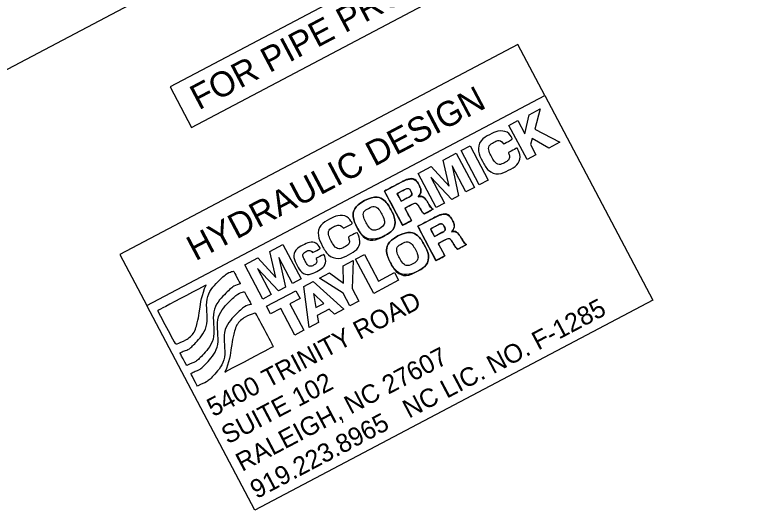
# Model space of a CAD drawing. Extents: x 1487051 to 1489241, y 497582 to 499399.
# Drawn here: x 1489072.9 to 1489240.5, y 498334.8 to 498446.4 of the extents above; entities that cross this region are included whole.
import ezdxf

# ---------------------------------------------------------------- set-up
doc = ezdxf.new("R2010")
doc.units = 0
doc.layers.add('COGO Default Point Elevation', color=7, linetype='Continuous')
doc.layers.add('Exist Vegetation Woods Line Cogo Elevation', color=7, linetype='Continuous')

msp = doc.modelspace()

# ---------------------------------------------------------------- linework, layer by layer
at = {"layer": 'Exist Vegetation Woods Line Cogo Elevation'}
for p, q in [((1489188.74, 498423.91), (1489191.24, 498425.23)), ((1489191.24, 498425.23), (1489189.99, 498420.68)), ((1489184.19, 498421.51), (1489186.2, 498422.57)), ((1489186.2, 498422.57), (1489187.76, 498419.61)), ((1489187.76, 498419.61), (1489188.74, 498423.91)), ((1489188.26, 498413.79), (1489184.19, 498421.51)), ((1489189.99, 498420.68), (1489195.67, 498417.7)), ((1489189.38, 498418.53), (1489189.02, 498417.23)), ((1489193.17, 498416.38), (1489189.38, 498418.53)), ((1489195.67, 498417.7), (1489193.17, 498416.38)), ((1489173.44, 498415.83), (1489175.45, 498416.89)), ((1489177.51, 498408.11), (1489173.44, 498415.83)), ((1489175.45, 498416.89), (1489179.52, 498409.17)), ((1489189.02, 498417.23), (1489190.27, 498414.85)), ((1489169.35, 498413.67), (1489172.31, 498415.24)), ((1489172.31, 498415.24), (1489176.39, 498407.52)), ((1489190.27, 498414.85), (1489188.26, 498413.79)), ((1489163.71, 498410.69), (1489166.67, 498412.26)), ((1489166.67, 498412.26), (1489170.72, 498407.81)), ((1489170.74, 498407.82), (1489169.35, 498413.67)), ((1489171.4, 498412.38), (1489171.38, 498412.37)), ((1489171.38, 498412.37), (1489172.85, 498405.65)), ((1489174.5, 498406.52), (1489171.4, 498412.38)), ((1489167.78, 498402.97), (1489163.71, 498410.69)), ((1489166.6, 498409.84), (1489166.58, 498409.83)), ((1489166.58, 498409.83), (1489169.67, 498403.97)), ((1489171.32, 498404.84), (1489166.6, 498409.84)), ((1489179.52, 498409.17), (1489177.51, 498408.11)), ((1489170.72, 498407.81), (1489170.74, 498407.82)), ((1489176.39, 498407.52), (1489174.5, 498406.52)), ((1489172.85, 498405.65), (1489171.32, 498404.84)), ((1489163.76, 498405.47), (1489163.77, 498405.44)), ((1489169.67, 498403.97), (1489167.78, 498402.97)), ((1489167.11, 498402.62), (1489165.12, 498401.57)), ((1489171.27, 498397.52), (1489171.28, 498397.49)), ((1489130.32, 498393.07), (1489133.29, 498394.63)), ((1489133.29, 498394.63), (1489137.36, 498386.91)), ((1489174.63, 498394.67), (1489172.64, 498393.62)), ((1489131.71, 498387.22), (1489130.32, 498393.07)), ((1489149.65, 498391.36), (1489151.66, 498392.42)), ((1489151.66, 498392.42), (1489154.83, 498386.43)), ((1489124.68, 498390.09), (1489127.64, 498391.65)), ((1489127.64, 498391.65), (1489131.69, 498387.21)), ((1489132.38, 498391.77), (1489132.35, 498391.76)), ((1489132.35, 498391.76), (1489133.83, 498385.04)), ((1489135.47, 498385.91), (1489132.38, 498391.77)), ((1489146.84, 498389.87), (1489149.12, 498391.08)), ((1489149.12, 498391.08), (1489148.87, 498384.75)), ((1489153.73, 498383.64), (1489149.65, 498391.36)), ((1489128.76, 498382.37), (1489124.68, 498390.09)), ((1489127.58, 498389.24), (1489127.55, 498389.23)), ((1489127.55, 498389.23), (1489130.65, 498383.37)), ((1489132.29, 498384.23), (1489127.58, 498389.24)), ((1489146.96, 498385.92), (1489146.84, 498389.87)), ((1489131.69, 498387.21), (1489131.71, 498387.22)), ((1489141.49, 498387.04), (1489143.77, 498388.25)), ((1489143.77, 498388.25), (1489146.96, 498385.92)), ((1489154.83, 498386.43), (1489158.43, 498388.33)), ((1489158.43, 498388.33), (1489159.34, 498386.6)), ((1489137.36, 498386.91), (1489135.47, 498385.91)), ((1489138.02, 498385.22), (1489140.07, 498386.29)), ((1489140.07, 498386.29), (1489147.03, 498380.1)), ((1489146.86, 498383.68), (1489141.49, 498387.04)), ((1489159.34, 498386.6), (1489153.73, 498383.64)), ((1489129.6, 498380.77), (1489136.22, 498384.26)), ((1489133.83, 498385.04), (1489132.29, 498384.23)), ((1489136.22, 498384.26), (1489137.13, 498382.53)), ((1489139.21, 498375.97), (1489138.02, 498385.22)), ((1489148.87, 498384.75), (1489150.39, 498381.87)), ((1489130.65, 498383.37), (1489128.76, 498382.37)), ((1489137.13, 498382.53), (1489134.83, 498381.32)), ((1489140.18, 498383.62), (1489140.16, 498383.61)), ((1489140.16, 498383.61), (1489140.71, 498380.44)), ((1489142.46, 498381.36), (1489140.18, 498383.62)), ((1489148.38, 498380.81), (1489146.86, 498383.68)), ((1489130.51, 498379.04), (1489129.6, 498380.77)), ((1489134.83, 498381.32), (1489137.99, 498375.33)), ((1489140.71, 498380.44), (1489142.46, 498381.36)), ((1489150.39, 498381.87), (1489148.38, 498380.81)), ((1489132.82, 498380.25), (1489130.51, 498379.04)), ((1489135.98, 498374.26), (1489132.82, 498380.25)), ((1489143.73, 498380.12), (1489141.03, 498378.7)), ((1489144.93, 498378.99), (1489143.73, 498380.12)), ((1489147.03, 498380.1), (1489144.93, 498378.99)), ((1489141.28, 498377.06), (1489139.21, 498375.97)), ((1489141.03, 498378.7), (1489141.28, 498377.06)), ((1489137.99, 498375.33), (1489135.98, 498374.26))]:
    msp.add_line(p, q, dxfattribs=at)
for points in [[(1488981.95, 498539.84), (1489169.07, 498638.65), (1489232.18, 498519.12), (1489045.06, 498420.32)], [(1489112.71, 498421.06), (1489240.52, 498488.55), (1489235.71, 498497.67), (1489107.89, 498430.18)], [(1489102.63, 498380.9), (1489192.24, 498428.21), (1489186.15, 498439.75), (1489096.54, 498392.43)], [(1489102.63, 498380.9), (1489192.24, 498428.21), (1489216.57, 498382.12), (1489126.97, 498334.81)]]:
    msp.add_lwpolyline(points, close=True, dxfattribs=at)
for points in [[(1489184.19, 498421.51), (1489186.2, 498422.57), (1489187.76, 498419.61), (1489188.74, 498423.91), (1489191.24, 498425.23), (1489189.99, 498420.68), (1489195.67, 498417.7), (1489193.17, 498416.38), (1489189.38, 498418.53), (1489189.02, 498417.23), (1489190.27, 498414.85), (1489188.26, 498413.79), (1489184.19, 498421.51)], [(1489173.44, 498415.83), (1489175.45, 498416.89), (1489179.52, 498409.17), (1489177.51, 498408.11), (1489173.44, 498415.83)], [(1489163.71, 498410.69), (1489166.67, 498412.26), (1489170.72, 498407.81), (1489170.74, 498407.82), (1489169.35, 498413.67), (1489172.31, 498415.24), (1489176.39, 498407.52), (1489174.5, 498406.52), (1489171.4, 498412.38), (1489171.38, 498412.37), (1489172.85, 498405.65), (1489171.32, 498404.84), (1489166.6, 498409.84), (1489166.58, 498409.83), (1489169.67, 498403.97), (1489167.78, 498402.97), (1489163.71, 498410.69)], [(1489162.29, 498403.67), (1489160.76, 498402.86), (1489162.25, 498400.05), (1489160.23, 498398.99), (1489156.16, 498406.71), (1489160.09, 498408.79)], [(1489160.62, 498407), (1489159.02, 498406.16), (1489159.94, 498404.42), (1489161.63, 498405.31)], [(1489169.8, 498395.72), (1489168.28, 498394.91), (1489169.76, 498392.1), (1489167.75, 498391.04), (1489163.67, 498398.76), (1489167.61, 498400.84)], [(1489168.14, 498399.05), (1489166.53, 498398.21), (1489167.45, 498396.47), (1489169.14, 498397.36)], [(1489124.68, 498390.09), (1489127.64, 498391.65), (1489131.69, 498387.21), (1489131.71, 498387.22), (1489130.32, 498393.07), (1489133.29, 498394.63), (1489137.36, 498386.91), (1489135.47, 498385.91), (1489132.38, 498391.77), (1489132.35, 498391.76), (1489133.83, 498385.04), (1489132.29, 498384.23), (1489127.58, 498389.24), (1489127.55, 498389.23), (1489130.65, 498383.37), (1489128.76, 498382.37), (1489124.68, 498390.09)], [(1489149.65, 498391.36), (1489151.66, 498392.42), (1489154.83, 498386.43), (1489158.43, 498388.33), (1489159.34, 498386.6), (1489153.73, 498383.64), (1489149.65, 498391.36)], [(1489148.87, 498384.75), (1489150.39, 498381.87), (1489148.38, 498380.81), (1489146.86, 498383.68), (1489141.49, 498387.04), (1489143.77, 498388.25), (1489146.96, 498385.92), (1489146.84, 498389.87), (1489149.12, 498391.08), (1489148.87, 498384.75)], [(1489138.02, 498385.22), (1489140.07, 498386.29), (1489147.03, 498380.1), (1489144.93, 498378.99), (1489143.73, 498380.12), (1489141.03, 498378.7), (1489141.28, 498377.06), (1489139.21, 498375.97), (1489138.02, 498385.22)], [(1489137.13, 498382.53), (1489134.83, 498381.32), (1489137.99, 498375.33), (1489135.98, 498374.26), (1489132.82, 498380.25), (1489130.51, 498379.04), (1489129.6, 498380.77), (1489136.22, 498384.26), (1489137.13, 498382.53)], [(1489140.71, 498380.44), (1489142.46, 498381.36), (1489140.18, 498383.62), (1489140.16, 498383.61), (1489140.71, 498380.44)]]:
    msp.add_lwpolyline(points, dxfattribs=at)
for points in [[(1489182.99, 498417.35), (1489182.47, 498418.07), (1489181.65, 498418.16), (1489180.81, 498417.72), (1489179.51, 498417.03), (1489179.62, 498415.62), (1489180.22, 498414.48), (1489180.83, 498413.33), (1489181.93, 498412.45), (1489183.23, 498413.13), (1489184.17, 498413.63), (1489184.42, 498414.46), (1489184.03, 498415.38), (1489184.03, 498415.38), (1489186.04, 498416.44), (1489186.04, 498416.44), (1489186.98, 498414.4), (1489186.14, 498412.46), (1489184.18, 498411.43), (1489181.85, 498410.19), (1489179.39, 498411.18), (1489178.21, 498413.42), (1489177.03, 498415.65), (1489177.6, 498418.24), (1489179.94, 498419.47), (1489181.6, 498420.35), (1489183.97, 498420.24), (1489185, 498418.41), (1489185, 498418.41), (1489182.99, 498417.35), (1489182.99, 498417.35)], [(1489182.99, 498417.35), (1489182.47, 498418.07), (1489181.65, 498418.16), (1489180.81, 498417.72), (1489179.51, 498417.03), (1489179.62, 498415.62), (1489180.22, 498414.48), (1489180.83, 498413.33), (1489181.93, 498412.45), (1489183.23, 498413.13), (1489184.17, 498413.63), (1489184.42, 498414.46), (1489184.03, 498415.38), (1489184.03, 498415.38), (1489186.04, 498416.44), (1489186.04, 498416.44), (1489186.98, 498414.4), (1489186.14, 498412.46), (1489184.18, 498411.43), (1489181.85, 498410.19), (1489179.39, 498411.18), (1489178.21, 498413.42), (1489177.03, 498415.65), (1489177.6, 498418.24), (1489179.94, 498419.47), (1489181.6, 498420.35), (1489183.97, 498420.24), (1489185, 498418.41), (1489185, 498418.41), (1489182.99, 498417.35), (1489182.99, 498417.35)], [(1489156.16, 498406.71), (1489156.16, 498406.71), (1489160.09, 498408.79), (1489160.09, 498408.79), (1489161.46, 498409.51), (1489163.12, 498409.6), (1489163.94, 498408.04), (1489164.38, 498407.21), (1489164.4, 498406.21), (1489163.76, 498405.47), (1489163.76, 498405.47), (1489163.77, 498405.44), (1489163.77, 498405.44), (1489164.69, 498405.68), (1489165.41, 498404.89), (1489165.87, 498404.19), (1489166.06, 498403.88), (1489166.69, 498402.76), (1489167.11, 498402.62), (1489167.11, 498402.62), (1489165.12, 498401.57), (1489165.12, 498401.57), (1489164.81, 498401.74), (1489164.38, 498402.48), (1489164.24, 498402.68), (1489163.78, 498403.43), (1489163.23, 498404.16), (1489162.29, 498403.67), (1489162.29, 498403.67), (1489160.76, 498402.86), (1489160.76, 498402.86), (1489160.76, 498402.86), (1489162.25, 498400.05), (1489162.25, 498400.05), (1489162.25, 498400.05), (1489160.23, 498398.99), (1489160.23, 498398.99), (1489160.23, 498398.99), (1489156.16, 498406.71), (1489156.16, 498406.71)], [(1489160.09, 498408.79), (1489161.46, 498409.51), (1489163.12, 498409.6), (1489163.94, 498408.04), (1489164.38, 498407.21), (1489164.4, 498406.21), (1489163.76, 498405.47)], [(1489159.94, 498404.42), (1489159.94, 498404.42), (1489161.63, 498405.31), (1489161.63, 498405.31), (1489162.23, 498405.63), (1489162.38, 498406.12), (1489162.08, 498406.71), (1489161.77, 498407.28), (1489161.18, 498407.3), (1489160.62, 498407), (1489160.62, 498407), (1489159.02, 498406.16), (1489159.02, 498406.16), (1489159.02, 498406.16), (1489159.94, 498404.42), (1489159.94, 498404.42)], [(1489161.63, 498405.31), (1489162.23, 498405.63), (1489162.38, 498406.12), (1489162.08, 498406.71), (1489161.77, 498407.28), (1489161.18, 498407.3), (1489160.62, 498407)], [(1489151.67, 498404.55), (1489154.1, 498405.83), (1489156.42, 498404.77), (1489157.6, 498402.53), (1489158.78, 498400.29), (1489158.35, 498397.79), (1489155.92, 498396.5), (1489153.48, 498395.22), (1489151.17, 498396.27), (1489149.99, 498398.51), (1489148.81, 498400.75), (1489149.24, 498403.26), (1489151.67, 498404.55)], [(1489151.67, 498404.55), (1489154.1, 498405.83), (1489156.42, 498404.77), (1489157.6, 498402.53), (1489158.78, 498400.29), (1489158.35, 498397.79), (1489155.92, 498396.5), (1489155.58, 498396.33), (1489155.25, 498396.19), (1489154.93, 498396.1)], [(1489163.77, 498405.44), (1489164.69, 498405.68), (1489165.41, 498404.89), (1489165.87, 498404.19), (1489166.06, 498403.88), (1489166.69, 498402.76), (1489167.11, 498402.62)], [(1489154.93, 498396.1), (1489152.87, 498395.53), (1489151.01, 498396.58), (1489149.99, 498398.51), (1489148.81, 498400.75), (1489149.24, 498403.26), (1489151.67, 498404.55)], [(1489165.12, 498401.57), (1489164.81, 498401.74), (1489164.38, 498402.48), (1489164.24, 498402.68), (1489163.78, 498403.43), (1489163.23, 498404.16), (1489162.29, 498403.67)], [(1489155, 498398.23), (1489156.3, 498398.92), (1489156.19, 498400.32), (1489155.59, 498401.47), (1489154.98, 498402.62), (1489153.88, 498403.5), (1489152.58, 498402.81), (1489151.29, 498402.13), (1489151.39, 498400.72), (1489152, 498399.58), (1489152.6, 498398.43), (1489153.71, 498397.55), (1489155, 498398.23)], [(1489155, 498398.23), (1489156.3, 498398.92), (1489156.19, 498400.32), (1489155.59, 498401.47), (1489154.98, 498402.62), (1489153.88, 498403.5), (1489152.58, 498402.81), (1489151.29, 498402.13), (1489151.39, 498400.72), (1489152, 498399.58), (1489152.6, 498398.43), (1489153.71, 498397.55), (1489155, 498398.23)], [(1489146.93, 498398.31), (1489146.41, 498399.03), (1489145.59, 498399.12), (1489144.74, 498398.68), (1489143.45, 498397.99), (1489143.55, 498396.58), (1489144.16, 498395.44), (1489144.76, 498394.29), (1489145.87, 498393.41), (1489147.16, 498394.09), (1489148.11, 498394.59), (1489148.36, 498395.41), (1489147.97, 498396.34), (1489147.97, 498396.34), (1489149.98, 498397.4), (1489149.98, 498397.4), (1489150.92, 498395.36), (1489150.08, 498393.42), (1489148.12, 498392.38), (1489145.79, 498391.15), (1489143.33, 498392.14), (1489142.15, 498394.37), (1489140.97, 498396.61), (1489141.54, 498399.2), (1489143.87, 498400.43), (1489145.54, 498401.31), (1489147.9, 498401.2), (1489148.94, 498399.37), (1489148.94, 498399.37), (1489146.93, 498398.31), (1489146.93, 498398.31)], [(1489146.93, 498398.31), (1489146.41, 498399.03), (1489145.59, 498399.12), (1489144.74, 498398.68), (1489143.45, 498397.99), (1489143.55, 498396.58), (1489144.16, 498395.44), (1489144.76, 498394.29), (1489145.87, 498393.41), (1489147.16, 498394.09), (1489148.11, 498394.59), (1489148.36, 498395.41), (1489147.97, 498396.34), (1489147.97, 498396.34), (1489149.98, 498397.4), (1489149.98, 498397.4), (1489150.92, 498395.36), (1489150.08, 498393.42), (1489148.12, 498392.38), (1489145.79, 498391.15), (1489143.33, 498392.14), (1489142.15, 498394.37), (1489140.97, 498396.61), (1489141.54, 498399.2), (1489143.87, 498400.43), (1489145.54, 498401.31), (1489147.9, 498401.2), (1489148.94, 498399.37), (1489148.94, 498399.37), (1489146.93, 498398.31), (1489146.93, 498398.31)], [(1489163.67, 498398.76), (1489163.67, 498398.76), (1489167.61, 498400.84), (1489167.61, 498400.84), (1489168.97, 498401.56), (1489170.64, 498401.65), (1489171.46, 498400.09), (1489171.9, 498399.26), (1489171.92, 498398.26), (1489171.27, 498397.52), (1489171.27, 498397.52), (1489171.28, 498397.49), (1489171.28, 498397.49), (1489172.21, 498397.73), (1489172.93, 498396.94), (1489173.38, 498396.24), (1489173.58, 498395.93), (1489174.21, 498394.81), (1489174.63, 498394.67), (1489174.63, 498394.67), (1489172.64, 498393.62), (1489172.64, 498393.62), (1489172.33, 498393.79), (1489171.89, 498394.53), (1489171.76, 498394.73), (1489171.29, 498395.48), (1489170.74, 498396.21), (1489169.8, 498395.72), (1489169.8, 498395.72), (1489168.28, 498394.91), (1489168.28, 498394.91), (1489168.28, 498394.91), (1489169.76, 498392.1), (1489169.76, 498392.1), (1489169.76, 498392.1), (1489167.75, 498391.04), (1489167.75, 498391.04), (1489167.75, 498391.04), (1489163.67, 498398.76), (1489163.67, 498398.76)], [(1489167.61, 498400.84), (1489168.97, 498401.56), (1489170.64, 498401.65), (1489171.46, 498400.09), (1489171.9, 498399.26), (1489171.92, 498398.26), (1489171.27, 498397.52)], [(1489167.45, 498396.47), (1489167.45, 498396.47), (1489169.14, 498397.36), (1489169.14, 498397.36), (1489169.75, 498397.68), (1489169.9, 498398.17), (1489169.59, 498398.76), (1489169.29, 498399.33), (1489168.7, 498399.35), (1489168.14, 498399.05), (1489168.14, 498399.05), (1489166.53, 498398.21), (1489166.53, 498398.21), (1489166.53, 498398.21), (1489167.45, 498396.47), (1489167.45, 498396.47)], [(1489169.14, 498397.36), (1489169.75, 498397.68), (1489169.9, 498398.17), (1489169.59, 498398.76), (1489169.29, 498399.33), (1489168.7, 498399.35), (1489168.14, 498399.05)], [(1489159.19, 498396.6), (1489161.63, 498397.89), (1489163.94, 498396.83), (1489165.12, 498394.59), (1489166.31, 498392.35), (1489165.88, 498389.84), (1489163.44, 498388.56), (1489161.01, 498387.27), (1489158.69, 498388.33), (1489157.51, 498390.57), (1489156.33, 498392.81), (1489156.76, 498395.32), (1489159.19, 498396.6)], [(1489159.19, 498396.6), (1489161.63, 498397.89), (1489163.94, 498396.83), (1489165.12, 498394.59), (1489166.31, 498392.35), (1489165.88, 498389.84), (1489163.44, 498388.56), (1489163.11, 498388.38), (1489162.78, 498388.25), (1489162.45, 498388.16)], [(1489171.28, 498397.49), (1489172.21, 498397.73), (1489172.93, 498396.94), (1489173.38, 498396.24), (1489173.58, 498395.93), (1489174.21, 498394.81), (1489174.63, 498394.67)], [(1489162.45, 498388.16), (1489160.4, 498387.58), (1489158.53, 498388.64), (1489157.51, 498390.57), (1489156.33, 498392.81), (1489156.76, 498395.32), (1489159.19, 498396.6)], [(1489172.64, 498393.62), (1489172.33, 498393.79), (1489171.89, 498394.53), (1489171.76, 498394.73), (1489171.29, 498395.48), (1489170.74, 498396.21), (1489169.8, 498395.72)], [(1489139.96, 498392.83), (1489139.7, 498393.3), (1489139.1, 498393.41), (1489138.63, 498393.17), (1489137.61, 498392.63), (1489137.91, 498391.66), (1489138.32, 498390.89), (1489138.7, 498390.16), (1489139.41, 498389.58), (1489140.19, 498389.99), (1489140.82, 498390.33), (1489140.95, 498390.87), (1489140.73, 498391.51), (1489140.73, 498391.51), (1489142.51, 498392.45), (1489142.51, 498392.45), (1489143.14, 498390.86), (1489142.43, 498389.38), (1489140.94, 498388.59), (1489139.25, 498387.7), (1489137.39, 498388.2), (1489136.48, 498389.91), (1489135.54, 498391.7), (1489136, 498393.57), (1489137.8, 498394.53), (1489139.2, 498395.26), (1489140.83, 498395.19), (1489141.74, 498393.77), (1489141.74, 498393.77), (1489139.96, 498392.83), (1489139.96, 498392.83)], [(1489139.96, 498392.83), (1489139.7, 498393.3), (1489139.1, 498393.41), (1489138.63, 498393.17), (1489137.61, 498392.63), (1489137.91, 498391.66), (1489138.32, 498390.89), (1489138.7, 498390.16), (1489139.41, 498389.58), (1489140.19, 498389.99), (1489140.82, 498390.33), (1489140.95, 498390.87), (1489140.73, 498391.51), (1489140.73, 498391.51), (1489142.51, 498392.45), (1489142.51, 498392.45), (1489143.14, 498390.86), (1489142.43, 498389.38), (1489140.94, 498388.59), (1489139.25, 498387.7), (1489137.39, 498388.2), (1489136.48, 498389.91), (1489135.54, 498391.7), (1489136, 498393.57), (1489137.8, 498394.53), (1489139.2, 498395.26), (1489140.83, 498395.19), (1489141.74, 498393.77), (1489141.74, 498393.77), (1489139.96, 498392.83), (1489139.96, 498392.83)], [(1489162.53, 498390.29), (1489163.83, 498390.97), (1489163.72, 498392.38), (1489163.11, 498393.53), (1489162.51, 498394.67), (1489161.41, 498395.56), (1489160.11, 498394.87), (1489158.81, 498394.19), (1489158.92, 498392.78), (1489159.52, 498391.63), (1489160.13, 498390.49), (1489161.23, 498389.6), (1489162.53, 498390.29)], [(1489162.53, 498390.29), (1489163.83, 498390.97), (1489163.72, 498392.38), (1489163.11, 498393.53), (1489162.51, 498394.67), (1489161.41, 498395.56), (1489160.11, 498394.87), (1489158.81, 498394.19), (1489158.92, 498392.78), (1489159.52, 498391.63), (1489160.13, 498390.49), (1489161.23, 498389.6), (1489162.53, 498390.29)], [(1489111.61, 498367.37), (1489112.6, 498367.9), (1489113.63, 498368.1), (1489115.2, 498369.69), (1489118.51, 498373.48), (1489116.83, 498379.94), (1489120.36, 498383.66), (1489122.28, 498385.5), (1489123.69, 498385.78), (1489123.69, 498385.78), (1489123.69, 498385.78), (1489122.18, 498388.64), (1489122.18, 498388.64), (1489122.18, 498388.64), (1489120.78, 498388.36), (1489118.85, 498386.52), (1489115.32, 498382.79), (1489117, 498376.34), (1489113.69, 498372.54), (1489112.12, 498370.96), (1489111.09, 498370.75), (1489110.1, 498370.23), (1489110.1, 498370.23), (1489111.61, 498367.37), (1489111.61, 498367.37)], [(1489111.61, 498367.37), (1489112.6, 498367.9), (1489113.63, 498368.1), (1489115.2, 498369.69), (1489118.51, 498373.48), (1489116.83, 498379.94), (1489120.36, 498383.66), (1489122.28, 498385.5), (1489123.69, 498385.78), (1489123.69, 498385.78), (1489123.69, 498385.78), (1489122.18, 498388.64), (1489122.18, 498388.64), (1489122.18, 498388.64), (1489120.78, 498388.36), (1489118.85, 498386.52), (1489115.32, 498382.79), (1489117, 498376.34), (1489113.69, 498372.54), (1489112.12, 498370.96), (1489111.09, 498370.75), (1489110.1, 498370.23), (1489110.1, 498370.23), (1489111.61, 498367.37), (1489111.61, 498367.37)], [(1489116, 498385.52), (1489114.97, 498383.39), (1489114.49, 498379.3), (1489114.2, 498377.95), (1489113.48, 498374.62), (1489111.48, 498373.08), (1489109.08, 498372.16), (1489109.08, 498372.16), (1489105.07, 498379.75), (1489105.07, 498379.75), (1489105.07, 498379.75), (1489116, 498385.52), (1489116, 498385.52)], [(1489116, 498385.52), (1489114.97, 498383.39), (1489114.49, 498379.3), (1489114.2, 498377.95), (1489113.48, 498374.62), (1489111.48, 498373.08), (1489109.08, 498372.16), (1489109.08, 498372.16), (1489105.07, 498379.75), (1489105.07, 498379.75), (1489105.07, 498379.75), (1489116, 498385.52), (1489116, 498385.52)], [(1489114.04, 498362.76), (1489115.04, 498363.28), (1489116.07, 498363.49), (1489117.64, 498365.07), (1489120.95, 498368.86), (1489119.26, 498375.32), (1489122.8, 498379.04), (1489124.72, 498380.88), (1489126.13, 498381.16), (1489126.13, 498381.16), (1489126.13, 498381.16), (1489124.62, 498384.02), (1489124.62, 498384.02), (1489124.62, 498384.02), (1489123.21, 498383.74), (1489121.29, 498381.9), (1489117.76, 498378.18), (1489119.44, 498371.72), (1489116.13, 498367.93), (1489114.56, 498366.34), (1489113.53, 498366.14), (1489112.54, 498365.61), (1489112.54, 498365.61), (1489114.04, 498362.76), (1489114.04, 498362.76)], [(1489114.04, 498362.76), (1489115.04, 498363.28), (1489116.07, 498363.49), (1489117.64, 498365.07), (1489120.95, 498368.86), (1489119.26, 498375.32), (1489122.8, 498379.04), (1489124.72, 498380.88), (1489126.13, 498381.16), (1489126.13, 498381.16), (1489126.13, 498381.16), (1489124.62, 498384.02), (1489124.62, 498384.02), (1489124.62, 498384.02), (1489123.21, 498383.74), (1489121.29, 498381.9), (1489117.76, 498378.18), (1489119.44, 498371.72), (1489116.13, 498367.93), (1489114.56, 498366.34), (1489113.53, 498366.14), (1489112.54, 498365.61), (1489112.54, 498365.61), (1489114.04, 498362.76), (1489114.04, 498362.76)], [(1489120.2, 498365.93), (1489121.23, 498368.06), (1489121.71, 498372.15), (1489122, 498373.5), (1489122.72, 498376.83), (1489124.72, 498378.37), (1489127.12, 498379.29), (1489127.12, 498379.29), (1489131.13, 498371.7), (1489131.13, 498371.7), (1489131.13, 498371.7), (1489120.2, 498365.93), (1489120.2, 498365.93)], [(1489120.2, 498365.93), (1489121.23, 498368.06), (1489121.71, 498372.15), (1489122, 498373.5), (1489122.72, 498376.83), (1489124.72, 498378.37), (1489127.12, 498379.29), (1489127.12, 498379.29), (1489131.13, 498371.7), (1489131.13, 498371.7), (1489131.13, 498371.7), (1489120.2, 498365.93), (1489120.2, 498365.93)]]:
    msp.add_open_spline(points, degree=3, dxfattribs=at)

# ---------------------------------------------------------------- texts
at = {"layer": 'COGO Default Point Elevation'}
for s, p in [('FOR PIPE PROFILE SEE SHEET 2D-1.', (1489114.34, 498424.87)), ('HYDRAULIC DESIGN', (1489113.58, 498390.87))]:
    msp.add_text(s, height=5.625, rotation=27.8351, dxfattribs=at).set_placement(p)
at = {"layer": 'Exist Vegetation Woods Line Cogo Elevation'}
for s, height, p in [('5400 TRINITY ROAD', 4.1773, (1489117.59, 498355.73)), ('919.223.8965   NC LIC. NO. F-1285', 4.1773, (1489127.34, 498337.26)), ('RALEIGH, NC 27607', 4.1773, (1489124.09, 498343.41)), ('SUITE 102', 4.177, (1489120.84, 498349.57))]:
    msp.add_text(s, height=height, rotation=27.8351, dxfattribs=at).set_placement(p)

doc.saveas('drawing.dxf')
